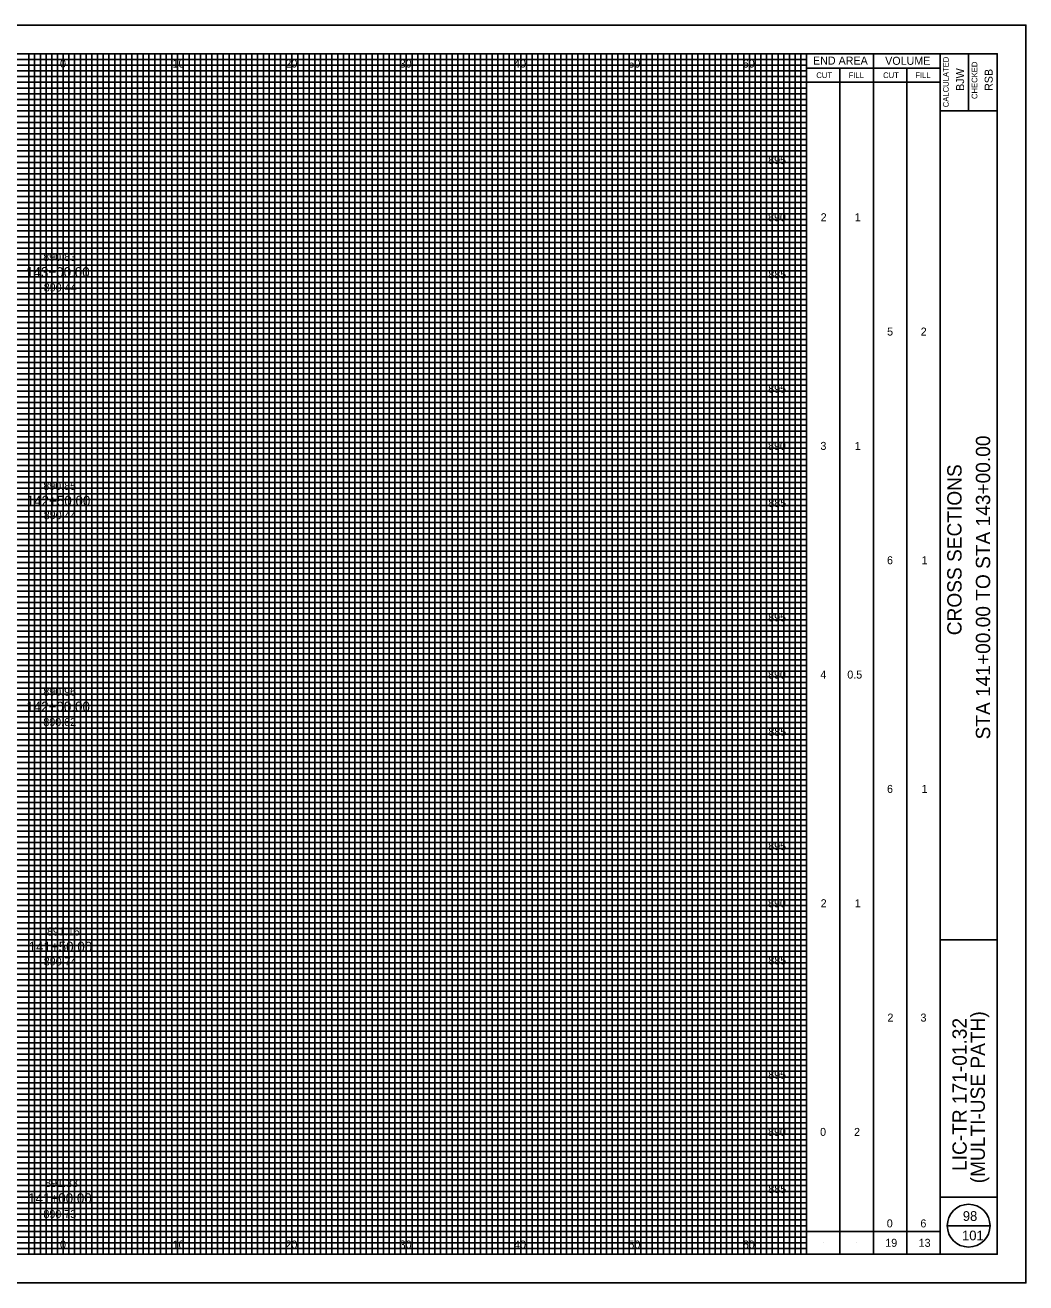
# Model space of a CAD drawing. Extents: x -10 to 160, y -2 to 3672.
# Drawn here: x 72.5 to 160, y 3332.5 to 3442.5 of the extents above; entities that cross this region are included whole.
import ezdxf

# ---------------------------------------------------------------- set-up
doc = ezdxf.new("R2010")
doc.units = 0
for name, color, linetype in [('SH_Border', 7, 'Continuous'), ('SH_Cut_Line', 7, 'Continuous'), ('SH_Data', 7, 'Continuous'), ('SH_Major_Grid_Line', 7, 'Continuous'), ('SH_Minor_Grid_Line', 7, 'Continuous'), ('SH_Text', 7, 'Continuous'), ('TX_P_10', 7, 'Continuous'), ('TX_X_10', 7, 'Continuous')]:
    doc.layers.add(name, color=color, linetype=linetype)

msp = doc.modelspace()

# ---------------------------------------------------------------- linework, layer by layer
at = {"layer": 'SH_Border'}
for p, q in [((152.5, 3335), (152.5, 3440)), ((155, 3440), (155, 3435)), ((152.5, 3435), (157.5, 3435)), ((152.5, 3362.5), (157.5, 3362.5)), ((152.5, 3340), (157.5, 3340))]:
    msp.add_line(p, q, dxfattribs=at)
msp.add_lwpolyline([(0, 3440), (157.5, 3440), (157.5, 3335), (0, 3335)], close=True, dxfattribs=at)
at = {"layer": 'SH_Cut_Line'}
msp.add_lwpolyline([(-10, 3332.5), (160, 3332.5), (160, 3442.5), (-10, 3442.5)], close=True, dxfattribs=at)
at = {"layer": 'SH_Data'}
for p, q in [((140.83, 3335), (140.83, 3440)), ((146.67, 3335), (146.67, 3440)), ((140.83, 3438.75), (152.5, 3438.75)), ((143.75, 3335), (143.75, 3438.75)), ((149.58, 3335), (149.58, 3438.75)), ((140.83, 3437.5), (152.5, 3437.5)), ((153.12, 3337.5), (156.88, 3337.5)), ((140.83, 3337), (152.5, 3337)), ((142.29, 3336), (142.29, 3336)), ((145.21, 3336), (145.21, 3336)), ((148.12, 3336), (148.12, 3336)), ((151.04, 3336), (151.04, 3336))]:
    msp.add_line(p, q, dxfattribs=at)
msp.add_circle((155, 3337.5), 1.87, dxfattribs=at)
at = {"layer": 'SH_Major_Grid_Line'}
for p, q in [((75.83, 3335), (75.83, 3440)), ((80.83, 3335), (80.83, 3440)), ((85.83, 3335), (85.83, 3440)), ((90.83, 3335), (90.83, 3440)), ((95.83, 3335), (95.83, 3440)), ((100.83, 3335), (100.83, 3440)), ((105.83, 3335), (105.83, 3440)), ((110.83, 3335), (110.83, 3440)), ((115.83, 3335), (115.83, 3440)), ((120.83, 3335), (120.83, 3440)), ((125.83, 3335), (125.83, 3440)), ((130.83, 3335), (130.83, 3440)), ((135.83, 3335), (135.83, 3440)), ((5.83, 3435), (140.83, 3435)), ((5.83, 3430), (140.83, 3430)), ((5.83, 3425), (140.83, 3425)), ((5.83, 3420), (140.83, 3420)), ((5.83, 3415), (140.83, 3415)), ((5.83, 3410), (140.83, 3410)), ((5.83, 3405), (140.83, 3405)), ((5.83, 3400), (140.83, 3400)), ((5.83, 3395), (140.83, 3395)), ((5.83, 3390), (140.83, 3390)), ((5.83, 3385), (140.83, 3385)), ((5.83, 3380), (140.83, 3380)), ((5.83, 3375), (140.83, 3375)), ((5.83, 3370), (140.83, 3370)), ((5.83, 3365), (140.83, 3365)), ((5.83, 3360), (140.83, 3360)), ((5.83, 3355), (140.83, 3355)), ((5.83, 3350), (140.83, 3350)), ((5.83, 3345), (140.83, 3345)), ((5.83, 3340), (140.83, 3340))]:
    msp.add_line(p, q, dxfattribs=at)
at = {"layer": 'SH_Minor_Grid_Line'}
for p, q in [((72.83, 3335), (72.83, 3440)), ((73.33, 3335), (73.33, 3440)), ((73.83, 3335), (73.83, 3440)), ((74.33, 3335), (74.33, 3440)), ((74.83, 3335), (74.83, 3440)), ((75.33, 3335), (75.33, 3440)), ((76.33, 3335), (76.33, 3440)), ((76.83, 3335), (76.83, 3440)), ((77.33, 3335), (77.33, 3440)), ((77.83, 3335), (77.83, 3440)), ((78.33, 3335), (78.33, 3440)), ((78.83, 3335), (78.83, 3440)), ((79.33, 3335), (79.33, 3440)), ((79.83, 3335), (79.83, 3440)), ((80.33, 3335), (80.33, 3440)), ((81.33, 3335), (81.33, 3440)), ((81.83, 3335), (81.83, 3440)), ((82.33, 3335), (82.33, 3440)), ((82.83, 3335), (82.83, 3440)), ((83.33, 3335), (83.33, 3440)), ((83.83, 3335), (83.83, 3440)), ((84.33, 3335), (84.33, 3440)), ((84.83, 3335), (84.83, 3440)), ((85.33, 3335), (85.33, 3440)), ((86.33, 3335), (86.33, 3440)), ((86.83, 3335), (86.83, 3440)), ((87.33, 3335), (87.33, 3440)), ((87.83, 3335), (87.83, 3440)), ((88.33, 3335), (88.33, 3440)), ((88.83, 3335), (88.83, 3440)), ((89.33, 3335), (89.33, 3440)), ((89.83, 3335), (89.83, 3440)), ((90.33, 3335), (90.33, 3440)), ((91.33, 3335), (91.33, 3440)), ((91.83, 3335), (91.83, 3440)), ((92.33, 3335), (92.33, 3440)), ((92.83, 3335), (92.83, 3440)), ((93.33, 3335), (93.33, 3440)), ((93.83, 3335), (93.83, 3440)), ((94.33, 3335), (94.33, 3440)), ((94.83, 3335), (94.83, 3440)), ((95.33, 3335), (95.33, 3440)), ((96.33, 3335), (96.33, 3440)), ((96.83, 3335), (96.83, 3440)), ((97.33, 3335), (97.33, 3440)), ((97.83, 3335), (97.83, 3440)), ((98.33, 3335), (98.33, 3440)), ((98.83, 3335), (98.83, 3440)), ((99.33, 3335), (99.33, 3440)), ((99.83, 3335), (99.83, 3440)), ((100.33, 3335), (100.33, 3440)), ((101.33, 3335), (101.33, 3440)), ((101.83, 3335), (101.83, 3440)), ((102.33, 3335), (102.33, 3440)), ((102.83, 3335), (102.83, 3440)), ((103.33, 3335), (103.33, 3440)), ((103.83, 3335), (103.83, 3440)), ((104.33, 3335), (104.33, 3440)), ((104.83, 3335), (104.83, 3440)), ((105.33, 3335), (105.33, 3440)), ((106.33, 3335), (106.33, 3440)), ((106.83, 3335), (106.83, 3440)), ((107.33, 3335), (107.33, 3440)), ((107.83, 3335), (107.83, 3440)), ((108.33, 3335), (108.33, 3440)), ((108.83, 3335), (108.83, 3440)), ((109.33, 3335), (109.33, 3440)), ((109.83, 3335), (109.83, 3440)), ((110.33, 3335), (110.33, 3440)), ((111.33, 3335), (111.33, 3440)), ((111.83, 3335), (111.83, 3440)), ((112.33, 3335), (112.33, 3440)), ((112.83, 3335), (112.83, 3440)), ((113.33, 3335), (113.33, 3440)), ((113.83, 3335), (113.83, 3440)), ((114.33, 3335), (114.33, 3440)), ((114.83, 3335), (114.83, 3440)), ((115.33, 3335), (115.33, 3440)), ((116.33, 3335), (116.33, 3440)), ((116.83, 3335), (116.83, 3440)), ((117.33, 3335), (117.33, 3440)), ((117.83, 3335), (117.83, 3440)), ((118.33, 3335), (118.33, 3440)), ((118.83, 3335), (118.83, 3440)), ((119.33, 3335), (119.33, 3440)), ((119.83, 3335), (119.83, 3440)), ((120.33, 3335), (120.33, 3440)), ((121.33, 3335), (121.33, 3440)), ((121.83, 3335), (121.83, 3440)), ((122.33, 3335), (122.33, 3440)), ((122.83, 3335), (122.83, 3440)), ((123.33, 3335), (123.33, 3440)), ((123.83, 3335), (123.83, 3440)), ((124.33, 3335), (124.33, 3440)), ((124.83, 3335), (124.83, 3440)), ((125.33, 3335), (125.33, 3440)), ((126.33, 3335), (126.33, 3440)), ((126.83, 3335), (126.83, 3440)), ((127.33, 3335), (127.33, 3440)), ((127.83, 3335), (127.83, 3440)), ((128.33, 3335), (128.33, 3440)), ((128.83, 3335), (128.83, 3440)), ((129.33, 3335), (129.33, 3440)), ((129.83, 3335), (129.83, 3440)), ((130.33, 3335), (130.33, 3440)), ((131.33, 3335), (131.33, 3440)), ((131.83, 3335), (131.83, 3440)), ((132.33, 3335), (132.33, 3440)), ((132.83, 3335), (132.83, 3440)), ((133.33, 3335), (133.33, 3440)), ((133.83, 3335), (133.83, 3440)), ((134.33, 3335), (134.33, 3440)), ((134.83, 3335), (134.83, 3440)), ((135.33, 3335), (135.33, 3440)), ((136.33, 3335), (136.33, 3440)), ((136.83, 3335), (136.83, 3440)), ((137.33, 3335), (137.33, 3440)), ((137.83, 3335), (137.83, 3440)), ((138.33, 3335), (138.33, 3440)), ((138.83, 3335), (138.83, 3440)), ((139.33, 3335), (139.33, 3440)), ((139.83, 3335), (139.83, 3440)), ((140.33, 3335), (140.33, 3440)), ((5.83, 3439.5), (140.83, 3439.5)), ((5.83, 3439), (140.83, 3439)), ((5.83, 3438.5), (140.83, 3438.5)), ((5.83, 3438), (140.83, 3438)), ((5.83, 3437.5), (140.83, 3437.5)), ((5.83, 3437), (140.83, 3437)), ((5.83, 3436.5), (140.83, 3436.5)), ((5.83, 3436), (140.83, 3436)), ((5.83, 3435.5), (140.83, 3435.5)), ((5.83, 3434.5), (140.83, 3434.5)), ((5.83, 3434), (140.83, 3434)), ((5.83, 3433.5), (140.83, 3433.5)), ((5.83, 3433), (140.83, 3433)), ((5.83, 3432.5), (140.83, 3432.5)), ((5.83, 3432), (140.83, 3432)), ((5.83, 3431.5), (140.83, 3431.5)), ((5.83, 3431), (140.83, 3431)), ((5.83, 3430.5), (140.83, 3430.5)), ((5.83, 3429.5), (140.83, 3429.5)), ((5.83, 3429), (140.83, 3429)), ((5.83, 3428.5), (140.83, 3428.5)), ((5.83, 3428), (140.83, 3428)), ((5.83, 3427.5), (140.83, 3427.5)), ((5.83, 3427), (140.83, 3427)), ((5.83, 3426.5), (140.83, 3426.5)), ((5.83, 3426), (140.83, 3426)), ((5.83, 3425.5), (140.83, 3425.5)), ((5.83, 3424.5), (140.83, 3424.5)), ((5.83, 3424), (140.83, 3424)), ((5.83, 3423.5), (140.83, 3423.5)), ((5.83, 3423), (140.83, 3423)), ((5.83, 3422.5), (140.83, 3422.5)), ((5.83, 3422), (140.83, 3422)), ((5.83, 3421.5), (140.83, 3421.5)), ((5.83, 3421), (140.83, 3421)), ((5.83, 3420.5), (140.83, 3420.5)), ((5.83, 3419.5), (140.83, 3419.5)), ((5.83, 3419), (140.83, 3419)), ((5.83, 3418.5), (140.83, 3418.5)), ((5.83, 3418), (140.83, 3418)), ((5.83, 3417.5), (140.83, 3417.5)), ((5.83, 3417), (140.83, 3417)), ((5.83, 3416.5), (140.83, 3416.5)), ((5.83, 3416), (140.83, 3416)), ((5.83, 3415.5), (140.83, 3415.5)), ((5.83, 3414.5), (140.83, 3414.5)), ((5.83, 3414), (140.83, 3414)), ((5.83, 3413.5), (140.83, 3413.5)), ((5.83, 3413), (140.83, 3413)), ((5.83, 3412.5), (140.83, 3412.5)), ((5.83, 3412), (140.83, 3412)), ((5.83, 3411.5), (140.83, 3411.5)), ((5.83, 3411), (140.83, 3411)), ((5.83, 3410.5), (140.83, 3410.5)), ((5.83, 3409.5), (140.83, 3409.5)), ((5.83, 3409), (140.83, 3409)), ((5.83, 3408.5), (140.83, 3408.5)), ((5.83, 3408), (140.83, 3408)), ((5.83, 3407.5), (140.83, 3407.5)), ((5.83, 3407), (140.83, 3407)), ((5.83, 3406.5), (140.83, 3406.5)), ((5.83, 3406), (140.83, 3406)), ((5.83, 3405.5), (140.83, 3405.5)), ((5.83, 3404.5), (140.83, 3404.5)), ((5.83, 3404), (140.83, 3404)), ((5.83, 3403.5), (140.83, 3403.5)), ((5.83, 3403), (140.83, 3403)), ((5.83, 3402.5), (140.83, 3402.5)), ((5.83, 3402), (140.83, 3402)), ((5.83, 3401.5), (140.83, 3401.5)), ((5.83, 3401), (140.83, 3401)), ((5.83, 3400.5), (140.83, 3400.5)), ((5.83, 3399.5), (140.83, 3399.5)), ((5.83, 3399), (140.83, 3399)), ((5.83, 3398.5), (140.83, 3398.5)), ((5.83, 3398), (140.83, 3398)), ((5.83, 3397.5), (140.83, 3397.5)), ((5.83, 3397), (140.83, 3397)), ((5.83, 3396.5), (140.83, 3396.5)), ((5.83, 3396), (140.83, 3396)), ((5.83, 3395.5), (140.83, 3395.5)), ((5.83, 3394.5), (140.83, 3394.5)), ((5.83, 3394), (140.83, 3394)), ((5.83, 3393.5), (140.83, 3393.5)), ((5.83, 3393), (140.83, 3393)), ((5.83, 3392.5), (140.83, 3392.5)), ((5.83, 3392), (140.83, 3392)), ((5.83, 3391.5), (140.83, 3391.5)), ((5.83, 3391), (140.83, 3391)), ((5.83, 3390.5), (140.83, 3390.5)), ((5.83, 3389.5), (140.83, 3389.5)), ((5.83, 3389), (140.83, 3389)), ((5.83, 3388.5), (140.83, 3388.5)), ((5.83, 3388), (140.83, 3388)), ((5.83, 3387.5), (140.83, 3387.5)), ((5.83, 3387), (140.83, 3387)), ((5.83, 3386.5), (140.83, 3386.5)), ((5.83, 3386), (140.83, 3386)), ((5.83, 3385.5), (140.83, 3385.5)), ((5.83, 3384.5), (140.83, 3384.5)), ((5.83, 3384), (140.83, 3384)), ((5.83, 3383.5), (140.83, 3383.5)), ((5.83, 3383), (140.83, 3383)), ((5.83, 3382.5), (140.83, 3382.5)), ((5.83, 3382), (140.83, 3382)), ((5.83, 3381.5), (140.83, 3381.5)), ((5.83, 3381), (140.83, 3381)), ((5.83, 3380.5), (140.83, 3380.5)), ((5.83, 3379.5), (140.83, 3379.5)), ((5.83, 3379), (140.83, 3379)), ((5.83, 3378.5), (140.83, 3378.5)), ((5.83, 3378), (140.83, 3378)), ((5.83, 3377.5), (140.83, 3377.5)), ((5.83, 3377), (140.83, 3377)), ((5.83, 3376.5), (140.83, 3376.5)), ((5.83, 3376), (140.83, 3376)), ((5.83, 3375.5), (140.83, 3375.5)), ((5.83, 3374.5), (140.83, 3374.5)), ((5.83, 3374), (140.83, 3374)), ((5.83, 3373.5), (140.83, 3373.5)), ((5.83, 3373), (140.83, 3373)), ((5.83, 3372.5), (140.83, 3372.5)), ((5.83, 3372), (140.83, 3372)), ((5.83, 3371.5), (140.83, 3371.5)), ((5.83, 3371), (140.83, 3371)), ((5.83, 3370.5), (140.83, 3370.5)), ((5.83, 3369.5), (140.83, 3369.5)), ((5.83, 3369), (140.83, 3369)), ((5.83, 3368.5), (140.83, 3368.5)), ((5.83, 3368), (140.83, 3368)), ((5.83, 3367.5), (140.83, 3367.5)), ((5.83, 3367), (140.83, 3367)), ((5.83, 3366.5), (140.83, 3366.5)), ((5.83, 3366), (140.83, 3366)), ((5.83, 3365.5), (140.83, 3365.5)), ((5.83, 3364.5), (140.83, 3364.5)), ((5.83, 3364), (140.83, 3364)), ((5.83, 3363.5), (140.83, 3363.5)), ((5.83, 3363), (140.83, 3363)), ((5.83, 3362.5), (140.83, 3362.5)), ((5.83, 3362), (140.83, 3362)), ((5.83, 3361.5), (140.83, 3361.5)), ((5.83, 3361), (140.83, 3361)), ((5.83, 3360.5), (140.83, 3360.5)), ((5.83, 3359.5), (140.83, 3359.5)), ((5.83, 3359), (140.83, 3359)), ((5.83, 3358.5), (140.83, 3358.5)), ((5.83, 3358), (140.83, 3358)), ((5.83, 3357.5), (140.83, 3357.5)), ((5.83, 3357), (140.83, 3357)), ((5.83, 3356.5), (140.83, 3356.5)), ((5.83, 3356), (140.83, 3356)), ((5.83, 3355.5), (140.83, 3355.5)), ((5.83, 3354.5), (140.83, 3354.5)), ((5.83, 3354), (140.83, 3354)), ((5.83, 3353.5), (140.83, 3353.5)), ((5.83, 3353), (140.83, 3353)), ((5.83, 3352.5), (140.83, 3352.5)), ((5.83, 3352), (140.83, 3352)), ((5.83, 3351.5), (140.83, 3351.5)), ((5.83, 3351), (140.83, 3351)), ((5.83, 3350.5), (140.83, 3350.5)), ((5.83, 3349.5), (140.83, 3349.5)), ((5.83, 3349), (140.83, 3349)), ((5.83, 3348.5), (140.83, 3348.5)), ((5.83, 3348), (140.83, 3348)), ((5.83, 3347.5), (140.83, 3347.5)), ((5.83, 3347), (140.83, 3347)), ((5.83, 3346.5), (140.83, 3346.5)), ((5.83, 3346), (140.83, 3346)), ((5.83, 3345.5), (140.83, 3345.5)), ((5.83, 3344.5), (140.83, 3344.5)), ((5.83, 3344), (140.83, 3344)), ((5.83, 3343.5), (140.83, 3343.5)), ((5.83, 3343), (140.83, 3343)), ((5.83, 3342.5), (140.83, 3342.5)), ((5.83, 3342), (140.83, 3342)), ((5.83, 3341.5), (140.83, 3341.5)), ((5.83, 3341), (140.83, 3341)), ((5.83, 3340.5), (140.83, 3340.5)), ((5.83, 3339.5), (140.83, 3339.5)), ((5.83, 3339), (140.83, 3339)), ((5.83, 3338.5), (140.83, 3338.5)), ((5.83, 3338), (140.83, 3338)), ((5.83, 3337.5), (140.83, 3337.5)), ((5.83, 3337), (140.83, 3337)), ((5.83, 3336.5), (140.83, 3336.5)), ((5.83, 3336), (140.83, 3336)), ((5.83, 3335.5), (140.83, 3335.5))]:
    msp.add_line(p, q, dxfattribs=at)

# ---------------------------------------------------------------- texts
at = {"layer": 'SH_Data'}
for s, height, p in [('END AREA', 0.7, (141.39, 3439.05)), ('VOLUME', 0.7, (147.7, 3439.03)), ('CUT', 0.5, (141.68, 3437.87)), ('FILL', 0.5, (144.5, 3437.87)), ('CUT', 0.5, (147.52, 3437.87)), ('FILL', 0.5, (150.34, 3437.87)), ('98', 0.85, (154.49, 3337.92)), ('101', 0.85, (154.42, 3336.22))]:
    msp.add_text(s, height=height, dxfattribs=at).set_placement(p)
for s, height, p in [('CALCULATED', 0.5, (153.26, 3435.32)), ('BJW', 0.7, (154.6, 3436.75)), ('CHECKED', 0.5, (155.76, 3436.04)), ('RSB', 0.7, (157.1, 3436.75)), ('STA 141+00.00 TO STA 143+00.00', 1.25, (156.88, 3380.03)), ('CROSS SECTIONS', 1.25, (154.38, 3389.14)), ('(MULTI-USE PATH)', 1.25, (156.42, 3341.21)), ('LIC-TR 171-01.32', 1.25, (154.83, 3342.29))]:
    msp.add_text(s, height=height, rotation=90, dxfattribs=at).set_placement(p)
at = {"layer": 'SH_Text'}
for s, height, p in [('0', 0.7, (75.55, 3438.79)), ('10', 0.7, (85.39, 3438.79)), ('20', 0.7, (95.26, 3438.79)), ('30', 0.7, (105.25, 3438.79)), ('40', 0.7, (115.25, 3438.79)), ('50', 0.7, (125.25, 3438.79)), ('60', 0.7, (135.25, 3438.79)), ('895', 0.7, (137.47, 3430.35)), ('890', 0.7, (137.46, 3425.35)), ('2', 0.7, (142.06, 3425.35)), ('1', 0.7, (145.04, 3425.35)), ('143+00.00', 0.875, (72.58, 3420.46)), ('885', 0.7, (137.48, 3420.35)), ('5', 0.7, (147.87, 3415.35)), ('2', 0.7, (150.81, 3415.35)), ('895', 0.7, (137.47, 3410.35)), ('890', 0.7, (137.46, 3405.35)), ('3', 0.7, (142.04, 3405.35)), ('1', 0.7, (145.04, 3405.35)), ('142+50.00', 0.875, (72.64, 3400.46)), ('885', 0.7, (137.48, 3400.35)), ('6', 0.7, (147.86, 3395.35)), ('1', 0.7, (150.88, 3395.35)), ('895', 0.7, (137.47, 3390.35)), ('890', 0.7, (137.46, 3385.35)), ('4', 0.7, (142.03, 3385.35)), ('0.5', 0.7, (144.39, 3385.35)), ('142+00.00', 0.875, (72.6, 3382.46)), ('885', 0.7, (137.48, 3380.35)), ('6', 0.7, (147.86, 3375.35)), ('1', 0.7, (150.88, 3375.35)), ('895', 0.7, (137.47, 3370.35)), ('890', 0.7, (137.46, 3365.35)), ('2', 0.7, (142.06, 3365.35)), ('1', 0.7, (145.04, 3365.35)), ('141+50.00', 0.875, (72.8, 3361.46)), ('885', 0.7, (137.48, 3360.35)), ('2', 0.7, (147.9, 3355.35)), ('3', 0.7, (150.79, 3355.35)), ('895', 0.7, (137.47, 3350.35)), ('890', 0.7, (137.46, 3345.35)), ('0', 0.7, (142.01, 3345.35)), ('2', 0.7, (144.98, 3345.35)), ('885', 0.7, (137.48, 3340.35)), ('141+00.00', 0.875, (72.76, 3339.46)), ('0', 0.7, (147.84, 3337.35)), ('6', 0.7, (150.78, 3337.35)), ('19', 0.7, (147.71, 3335.65)), ('13', 0.7, (150.63, 3335.65)), ('0', 0.7, (75.55, 3335.5)), ('10', 0.7, (85.39, 3335.5)), ('20', 0.7, (95.26, 3335.5)), ('30', 0.7, (105.25, 3335.5)), ('40', 0.7, (115.25, 3335.5)), ('50', 0.7, (125.25, 3335.5)), ('60', 0.7, (135.25, 3335.5))]:
    msp.add_text(s, height=height, dxfattribs=at).set_placement(p)
at = {"layer": 'TX_P_10'}
for s, p in [('890.83', (74.08, 3421.88)), ('890.85', (74.09, 3401.85)), ('890.96', (74.09, 3383.86)), ('891.16', (74.41, 3362.88)), ('891.33', (74.25, 3340.88))]:
    msp.add_text(s, height=0.7, dxfattribs=at).set_placement(p)
at = {"layer": 'TX_X_10'}
for s, p in [('890.44', (74.13, 3419.21)), ('890.44', (74.13, 3399.29)), ('890.62', (74.09, 3381.2)), ('890.74', (74.13, 3360.26)), ('890.73', (74.1, 3338.17))]:
    msp.add_text(s, height=0.7, dxfattribs=at).set_placement(p)

doc.saveas('drawing.dxf')
